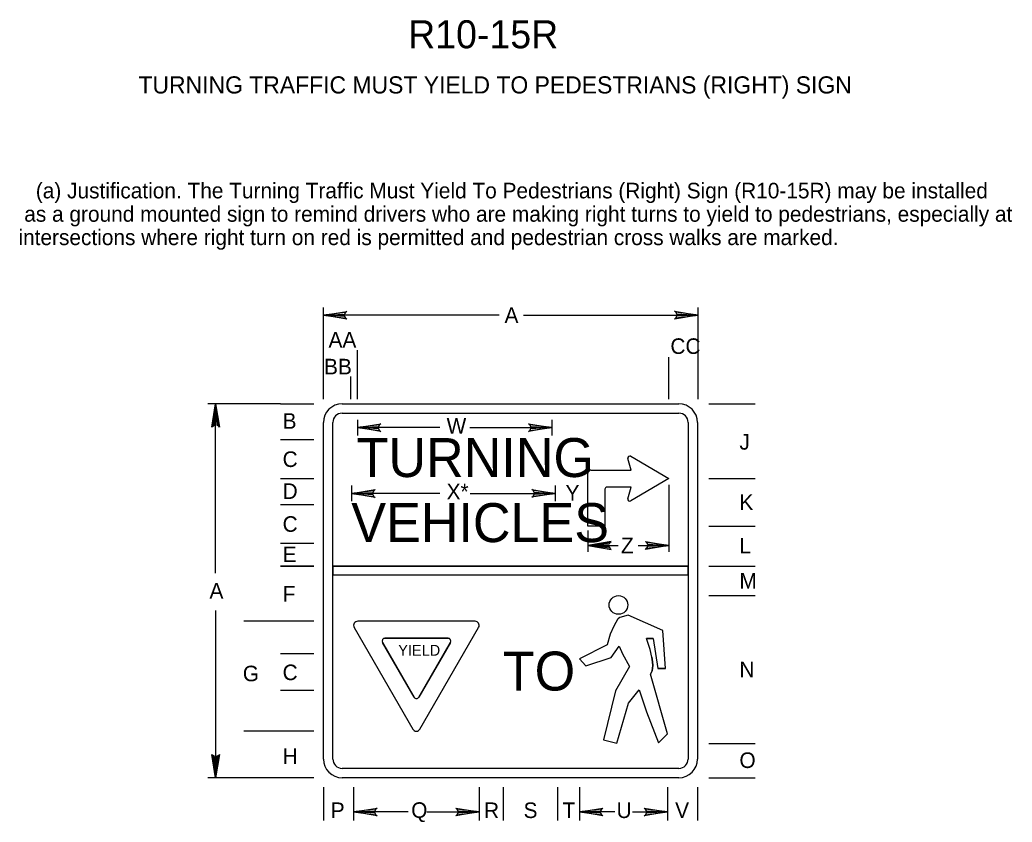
# Model space of a CAD drawing. Extents: x 0.013 to 0.195, y 0.003 to 0.259.
# Drawn here: x 0.0354 to 0.1946, y 0.1304 to 0.2592 of the extents above; entities that cross this region are included whole.
import ezdxf

# ---------------------------------------------------------------- set-up
doc = ezdxf.new("R2010")
doc.units = 0
for name, color, linetype in [('1', 7, 'Continuous'), ('11', 7, 'Continuous'), ('12', 7, 'Continuous'), ('2', 7, 'Continuous'), ('3', 7, 'Continuous')]:
    doc.layers.add(name, color=color, linetype=linetype)

# ---------------------------------------------------------------- blocks, each defined once
blk = doc.blocks.new('RARROW')
at = {"layer": '3'}
for p, q in [((-2.156, 0.28500000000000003), (-2.2665, 0.384625)), ((-2.2665, 0.384625), (0, 0)), ((0, 0), (-2.2665, -0.379125)), ((-2.156, 0.28500000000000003), (-2.075625, 0.12075)), ((0, 0), (-2.156, 0.28500000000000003)), ((-2.14975, -0.2705), (0, 0)), ((-2.075625, 0.12075), (0, 0)), ((0, 0), (-2.074, -0.108)), ((-2.2665, -0.379125), (-2.14975, -0.2705)), ((-2.074, -0.108), (-2.14975, -0.2705))]:
    blk.add_line(p, q, dxfattribs=at)

msp = doc.modelspace()

# ---------------------------------------------------------------- linework, layer by layer
at = {"layer": '11'}
for p, q in [((0.08714626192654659, 0.19757244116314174), (0.14114626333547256, 0.19757244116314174)), ((0.08414626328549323, 0.1405724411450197), (0.08414626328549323, 0.19457244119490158)), ((0.14414626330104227, 0.19457244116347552), (0.14414626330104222, 0.14057244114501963)), ((0.13352399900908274, 0.1869474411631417), (0.13298903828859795, 0.18879460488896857)), ((0.13344744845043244, 0.18915100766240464), (0.1395413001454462, 0.1855724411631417)), ((0.12654130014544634, 0.1779474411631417), (0.1265413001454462, 0.1864474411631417)), ((0.1270413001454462, 0.1869474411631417), (0.13352399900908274, 0.1869474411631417)), ((0.1395413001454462, 0.1855724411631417), (0.1334474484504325, 0.1819938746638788)), ((0.12929130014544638, 0.1838849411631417), (0.12929130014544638, 0.1779474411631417)), ((0.13352399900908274, 0.18419744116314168), (0.12960380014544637, 0.18419744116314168)), ((0.13298903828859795, 0.18235027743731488), (0.13352399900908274, 0.18419744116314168)), ((0.12929130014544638, 0.1779474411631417), (0.1265413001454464, 0.1779474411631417)), ((0.14114680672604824, 0.13757244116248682), (0.08714626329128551, 0.13757244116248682))]:
    msp.add_line(p, q, dxfattribs=at)
for centre, radius, start, end in [((0.08714626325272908, 0.19457244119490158), 0.002999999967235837, 90, 180), ((0.1411462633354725, 0.19457244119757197), 0.0029999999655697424, 0, 90), ((0.1332892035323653, 0.18888153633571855), 0.0003125, 59.57674888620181, 196.15164896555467), ((0.1270413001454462, 0.1864474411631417), 0.0005, 90, 180), ((0.12960380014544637, 0.1838849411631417), 0.0003125, 90, 180), ((0.13328920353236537, 0.18226334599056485), 0.0003125, 163.8483510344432, 300.4232511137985), ((0.08714626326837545, 0.1405724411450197), 0.0029999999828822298, 180, 270), ((0.14114626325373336, 0.1405724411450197), 0.003000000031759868, 270, 0)]:
    msp.add_arc(centre, radius, start, end, dxfattribs=at)
at = {"layer": '3'}
for p, q in [((0.08414367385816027, 0.19832244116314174), (0.08414367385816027, 0.21304199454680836)), ((0.11232555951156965, 0.21179199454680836), (0.08414367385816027, 0.21179199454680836)), ((0.11624734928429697, 0.21179199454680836), (0.14422597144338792, 0.21179199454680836)), ((0.14422597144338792, 0.19832244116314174), (0.14422597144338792, 0.21304199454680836)), ((0.08958818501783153, 0.19832244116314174), (0.08958818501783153, 0.206177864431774)), ((0.1395413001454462, 0.19832244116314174), (0.1395413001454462, 0.20505915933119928)), ((0.08853412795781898, 0.19832244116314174), (0.08853412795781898, 0.20194492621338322)), ((0.07725456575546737, 0.1975724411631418), (0.06559336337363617, 0.19757244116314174)), ((0.06621386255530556, 0.19382244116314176), (0.06684336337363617, 0.19757244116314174)), ((0.06684336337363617, 0.19757244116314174), (0.0663769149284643, 0.1940052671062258)), ((0.06664573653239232, 0.1941382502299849), (0.06684336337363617, 0.19757244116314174)), ((0.06684336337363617, 0.19757244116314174), (0.0670201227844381, 0.19414093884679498)), ((0.06728608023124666, 0.19401560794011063), (0.06684336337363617, 0.19757244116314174)), ((0.06684336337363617, 0.19757244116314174), (0.06746386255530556, 0.19382244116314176)), ((0.06684336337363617, 0.1704095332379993), (0.06684336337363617, 0.19757244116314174)), ((0.07725456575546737, 0.19757244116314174), (0.08260389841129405, 0.19757244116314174)), ((0.14597859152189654, 0.19757244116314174), (0.15337234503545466, 0.19757244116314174)), ((0.08714621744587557, 0.19607244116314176), (0.14114626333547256, 0.19607244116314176)), ((0.08564626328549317, 0.140572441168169), (0.08564626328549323, 0.19457244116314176)), ((0.08958818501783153, 0.19502509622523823), (0.08958818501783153, 0.19249982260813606)), ((0.12079452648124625, 0.19502509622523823), (0.12079452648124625, 0.19249982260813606)), ((0.14264626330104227, 0.19457244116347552), (0.14264626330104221, 0.14057244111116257)), ((0.0663769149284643, 0.1940052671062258), (0.06621386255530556, 0.19382244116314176)), ((0.0663769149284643, 0.1940052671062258), (0.06664573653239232, 0.1941382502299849)), ((0.0670201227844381, 0.19414093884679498), (0.06728608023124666, 0.19401560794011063)), ((0.06746386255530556, 0.19382244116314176), (0.06728608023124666, 0.19401560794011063)), ((0.0926263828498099, 0.19374917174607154), (0.08958818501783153, 0.19374917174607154)), ((0.10279613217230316, 0.19374917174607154), (0.08958818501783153, 0.19374917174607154)), ((0.1076093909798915, 0.19374917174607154), (0.12079452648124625, 0.19374917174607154)), ((0.07725456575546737, 0.1918396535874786), (0.08260389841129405, 0.1918396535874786)), ((0.07725456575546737, 0.18558926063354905), (0.08260389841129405, 0.18558926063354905)), ((0.14597859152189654, 0.1855724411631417), (0.15337234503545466, 0.18557221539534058)), ((0.0886643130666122, 0.18446330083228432), (0.0886643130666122, 0.18193802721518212)), ((0.10279613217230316, 0.18318737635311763), (0.0886643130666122, 0.18318737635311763)), ((0.0926263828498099, 0.18318737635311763), (0.08958818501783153, 0.18318737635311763)), ((0.10765501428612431, 0.18318802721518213), (0.12079452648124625, 0.18318802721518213)), ((0.12133060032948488, 0.18446330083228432), (0.12133060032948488, 0.18193802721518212)), ((0.1395413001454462, 0.18459410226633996), (0.1395413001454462, 0.1738092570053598)), ((0.07725456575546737, 0.1814033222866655), (0.08260389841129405, 0.1814033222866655)), ((0.1265413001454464, 0.1772487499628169), (0.1265413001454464, 0.1738092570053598)), ((0.14597859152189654, 0.1779474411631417), (0.15337234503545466, 0.1779474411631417)), ((0.07725456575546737, 0.17520995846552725), (0.08260389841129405, 0.17520995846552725)), ((0.1265413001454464, 0.17482786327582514), (0.13142869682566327, 0.17482786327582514)), ((0.13465260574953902, 0.17482786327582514), (0.13954000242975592, 0.17482786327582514)), ((0.07725456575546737, 0.1715372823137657), (0.08260389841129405, 0.1715372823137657)), ((0.08260389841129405, 0.17151328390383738), (0.07725456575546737, 0.17151328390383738)), ((0.08564626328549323, 0.17151328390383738), (0.14264626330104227, 0.17151328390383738)), ((0.08564626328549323, 0.17151328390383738), (0.14264626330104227, 0.17151328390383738)), ((0.14597859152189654, 0.1715372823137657), (0.15337234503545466, 0.1715372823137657)), ((0.08564626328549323, 0.1701387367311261), (0.14264626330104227, 0.1701387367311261)), ((0.14597859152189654, 0.16679245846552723), (0.15337234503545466, 0.16679245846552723)), ((0.06684336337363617, 0.16440728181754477), (0.06684336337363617, 0.13757244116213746)), ((0.08260389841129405, 0.16268525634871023), (0.07138468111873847, 0.16268525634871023)), ((0.10845774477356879, 0.16268525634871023), (0.0896450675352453, 0.16268525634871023)), ((0.13139105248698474, 0.16304309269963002), (0.1307183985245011, 0.16189648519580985)), ((0.13139105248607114, 0.16304309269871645), (0.1314746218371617, 0.16312666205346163)), ((0.13166439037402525, 0.16329738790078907), (0.13147462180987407, 0.16312666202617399)), ((0.13303157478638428, 0.16367847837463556), (0.13166439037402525, 0.16329738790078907)), ((0.13860080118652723, 0.16117027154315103), (0.13303157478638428, 0.16367847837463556)), ((0.08907250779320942, 0.1617037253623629), (0.09847884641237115, 0.14537214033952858)), ((0.09962396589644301, 0.14537214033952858), (0.10903030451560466, 0.1617037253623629)), ((0.1307183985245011, 0.16189648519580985), (0.1301372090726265, 0.1606256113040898)), ((0.13901126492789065, 0.15508652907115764), (0.13860080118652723, 0.16117027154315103)), ((0.09359845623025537, 0.15930442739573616), (0.09866969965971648, 0.1504979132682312)), ((0.10412264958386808, 0.15995878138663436), (0.09398016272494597, 0.15995878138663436)), ((0.09943311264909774, 0.1504979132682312), (0.10450435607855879, 0.15930442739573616)), ((0.1301372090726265, 0.1606256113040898), (0.12962866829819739, 0.1588826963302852)), ((0.13594911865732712, 0.15989939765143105), (0.13703885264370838, 0.15993570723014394)), ((0.1365666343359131, 0.1581564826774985), (0.13594911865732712, 0.15989939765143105)), ((0.13703885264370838, 0.15993570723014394), (0.1377912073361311, 0.15512137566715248)), ((0.13028250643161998, 0.1568492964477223), (0.13159018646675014, 0.15870114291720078)), ((0.13159018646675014, 0.15870114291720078), (0.13213505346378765, 0.1574302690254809)), ((0.1368439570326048, 0.15692897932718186), (0.1365666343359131, 0.1581564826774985)), ((0.08260389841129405, 0.15745674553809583), (0.07725456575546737, 0.15745674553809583)), ((0.1262133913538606, 0.15551470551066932), (0.13028250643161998, 0.1568492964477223)), ((0.13213505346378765, 0.1574302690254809), (0.13326110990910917, 0.15543317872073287)), ((0.13693632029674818, 0.15619034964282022), (0.1368439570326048, 0.15692897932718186)), ((0.1369653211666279, 0.15555974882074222), (0.13693632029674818, 0.15619034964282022)), ((0.13326110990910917, 0.15543317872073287), (0.1309937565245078, 0.1515322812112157)), ((0.13661346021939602, 0.15418801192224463), (0.13686855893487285, 0.1547331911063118)), ((0.13686855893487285, 0.1547331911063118), (0.1369653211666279, 0.15555974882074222)), ((0.1377912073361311, 0.15512137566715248), (0.13901126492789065, 0.15508652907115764)), ((0.13933463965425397, 0.14461041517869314), (0.13661346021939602, 0.15418801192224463)), ((0.08260389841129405, 0.15156691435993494), (0.07725456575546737, 0.15156691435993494)), ((0.1309937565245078, 0.1515322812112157), (0.12907652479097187, 0.14365718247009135)), ((0.13305042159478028, 0.14951123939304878), (0.13478673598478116, 0.15165686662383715)), ((0.13478673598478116, 0.15165686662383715), (0.135985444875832, 0.14817103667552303)), ((0.13120290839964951, 0.14309965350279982), (0.13305042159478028, 0.14951123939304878)), ((0.135985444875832, 0.14817103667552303), (0.13788983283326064, 0.1431478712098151)), ((0.08260389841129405, 0.14504147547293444), (0.07138468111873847, 0.14504147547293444)), ((0.12907652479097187, 0.14365718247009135), (0.13120290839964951, 0.14309965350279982)), ((0.13788983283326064, 0.1431478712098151), (0.13933463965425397, 0.14461041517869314)), ((0.14597859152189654, 0.14307974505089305), (0.15337234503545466, 0.14307974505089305)), ((0.14114664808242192, 0.13907244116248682), (0.08714626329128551, 0.13907244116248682)), ((0.07725456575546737, 0.13757244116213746), (0.06559336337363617, 0.13757244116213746)), ((0.08260389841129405, 0.13757244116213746), (0.07725456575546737, 0.13757244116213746)), ((0.14597859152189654, 0.1375724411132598), (0.15337234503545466, 0.1375724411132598)), ((0.08414626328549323, 0.13604448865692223), (0.08414626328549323, 0.13070656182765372)), ((0.0889899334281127, 0.13604448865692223), (0.0889907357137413, 0.13070656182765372)), ((0.10911631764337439, 0.13604448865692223), (0.10911624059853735, 0.13070656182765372)), ((0.11299472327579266, 0.13604448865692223), (0.11299472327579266, 0.13070656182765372)), ((0.12166315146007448, 0.13604448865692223), (0.12166315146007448, 0.13070656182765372)), ((0.12523045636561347, 0.13604448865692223), (0.12523045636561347, 0.13070656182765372)), ((0.13933463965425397, 0.13604448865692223), (0.13933463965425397, 0.13070656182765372)), ((0.14414626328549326, 0.13604448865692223), (0.14414626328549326, 0.13070656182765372)), ((0.09775368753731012, 0.1320796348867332), (0.08899052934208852, 0.1320796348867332)), ((0.1007284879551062, 0.13207591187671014), (0.10911626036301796, 0.13207591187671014)), ((0.13088887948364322, 0.1320796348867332), (0.12522462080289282, 0.1320796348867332)), ((0.1337444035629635, 0.13207591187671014), (0.13933463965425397, 0.13207591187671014))]:
    msp.add_line(p, q, dxfattribs=at)
for points in [[(0.08564626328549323, 0.1701387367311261), (0.14264626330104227, 0.1701387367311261), (0.1426462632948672, 0.17151328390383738), (0.08564626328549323, 0.17151328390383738), (0.08564626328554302, 0.1701387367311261)], [(0.10845774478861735, 0.1626852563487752), (0.0896450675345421, 0.16268525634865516)], [(0.08907250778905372, 0.16170372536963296), (0.09847884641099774, 0.14537214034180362)], [(0.09962396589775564, 0.14537214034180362), (0.10903030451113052, 0.16170372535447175)], [(0.09867564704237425, 0.15050856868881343), (0.09360463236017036, 0.1592930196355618)], [(0.09398249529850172, 0.1599472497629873), (0.10412502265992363, 0.1599472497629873)], [(0.10450293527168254, 0.15929310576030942), (0.0994309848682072, 0.15050896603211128)], [(0.13703885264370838, 0.15993570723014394), (0.13594911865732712, 0.15989939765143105), (0.13703885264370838, 0.15993570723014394)], [(0.12962866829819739, 0.1588826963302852), (0.12523045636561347, 0.15663506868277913), (0.1262133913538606, 0.15551470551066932)], [(0.1368439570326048, 0.15692897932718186), (0.13693632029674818, 0.15619034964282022), (0.1369653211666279, 0.15555974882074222), (0.13686855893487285, 0.1547331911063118), (0.13661346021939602, 0.15418801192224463), (0.13686855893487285, 0.1547331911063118), (0.1369653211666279, 0.15555974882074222), (0.13693632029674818, 0.15619034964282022), (0.1368439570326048, 0.15692897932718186)], [(0.13901126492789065, 0.15508652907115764), (0.1377912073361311, 0.15512137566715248), (0.13901126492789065, 0.15508652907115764)]]:
    msp.add_lwpolyline(points, dxfattribs=at)
msp.add_circle((0.1314666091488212, 0.16529132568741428), 0.0014959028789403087, dxfattribs=at)
for centre, radius, start, end in [((0.08714626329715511, 0.19457244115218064), 0.0015000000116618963, 90, 180), ((0.14114626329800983, 0.19457244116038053), 0.001500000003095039, 0, 90), ((0.08964201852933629, 0.16202927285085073), 0.0006559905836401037, 89.73369166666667, 209.75343333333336), ((0.08964201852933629, 0.16202927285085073), 0.0006559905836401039, 89.73369166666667, 209.75343333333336), ((0.10846057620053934, 0.16202914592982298), 0.0006561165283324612, 330.2656166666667, 90.24725555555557), ((0.10846057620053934, 0.16202914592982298), 0.0006561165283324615, 330.2656166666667, 90.24725555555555), ((0.09398249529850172, 0.1595110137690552), 0.0004362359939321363, 90, 209.98121666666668), ((0.09398249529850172, 0.1595110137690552), 0.0004362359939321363, 89.99999999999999, 209.98121666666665), ((0.10412502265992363, 0.1595110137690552), 0.0004362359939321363, 330.03184166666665, 90), ((0.10412502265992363, 0.1595110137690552), 0.0004362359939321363, 330.03184166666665, 89.99999999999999), ((0.0990532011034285, 0.15072709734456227), 0.00043623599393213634, 210.0623, 329.99798055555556), ((0.0990532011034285, 0.15072709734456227), 0.0004362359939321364, 210.06229999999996, 329.9979805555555), ((0.09905140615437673, 0.14570251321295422), 0.0006610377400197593, 209.9853888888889, 330.0146111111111), ((0.09905140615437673, 0.14570251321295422), 0.0006610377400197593, 209.98538888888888, 330.0146111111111), ((0.08714626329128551, 0.140572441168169), 0.001500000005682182, 180, 270), ((0.14114626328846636, 0.14057244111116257), 0.0014999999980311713, 270, 0)]:
    msp.add_arc(centre, radius, start, end, dxfattribs=at)

# ---------------------------------------------------------------- block references
at = {"layer": '3', "xscale": 0.0016545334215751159}
for p, yscale, rotation in [((0.08414367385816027, 0.21179199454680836), 0.0016366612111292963, 180), ((0.08958818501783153, 0.19374917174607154), 0.0016366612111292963, 180), ((0.0886643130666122, 0.18318737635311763), 0.0016366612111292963, 180), ((0.1265413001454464, 0.17482786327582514), -0.0016366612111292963, 180), ((0.06684336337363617, 0.13757244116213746), 0.0016366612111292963, -90), ((0.08899052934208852, 0.1320796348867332), 0.0016366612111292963, 180), ((0.12522462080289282, 0.1320796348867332), 0.0016366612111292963, 180)]:
    msp.add_blockref('RARROW', p, dxfattribs=dict(at, yscale=yscale, rotation=rotation))
at = {"layer": '3', "xscale": 0.0016545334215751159, "yscale": 0.0016366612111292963}
for p in [(0.14422597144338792, 0.21179199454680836), (0.1207945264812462, 0.19374917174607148), (0.12133060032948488, 0.18318802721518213), (0.13954000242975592, 0.17482786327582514), (0.10911626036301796, 0.13207591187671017), (0.13933463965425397, 0.13207591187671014)]:
    msp.add_blockref('RARROW', p, dxfattribs=at)

# ---------------------------------------------------------------- texts
at = {"layer": '1'}
for s, height, p in [('R10-15R', 0.0045000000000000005, (0.09772772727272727, 0.254625)), ('TURNING TRAFFIC MUST YIELD TO PEDESTRIANS (RIGHT) SIGN', 0.00275025, (0.05447118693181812, 0.247375))]:
    msp.add_text(s, height=height, dxfattribs=at).set_placement(p)
at = {"layer": '12'}
for s, p in [('TURNING', (0.08946536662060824, 0.18582526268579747)), ('VEHICLES', (0.08861025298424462, 0.17538260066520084)), ('TO', (0.11291575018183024, 0.15156490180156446))]:
    msp.add_text(s, height=0.0062499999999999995, dxfattribs=at).set_placement(p)
at = {"layer": '2'}
for s, p in [('   (a) Justification. The Turning Traffic Must Yield To Pedestrians (Right) Sign (R10-15R) may be installed ', (0.03522071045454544, 0.23054097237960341)), (' as a ground mounted sign to remind drivers who are making right turns to yield to pedestrians, especially at ', (0.03522071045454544, 0.2267912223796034)), ('intersections where right turn on red is permitted and pedestrian cross walks are marked.', (0.03522071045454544, 0.22304147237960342))]:
    msp.add_text(s, height=0.0024997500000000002, dxfattribs=at).set_placement(p)
at = {"layer": '3'}
for s, height, p in [('A', 0.0025, (0.11319020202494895, 0.21054199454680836)), ('AA', 0.0025, (0.08496031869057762, 0.20659481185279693)), ('CC', 0.0025, (0.13979731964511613, 0.2055789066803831)), ('BB', 0.0025, (0.08423998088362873, 0.20229535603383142)), ('B', 0.0024997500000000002, (0.07759461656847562, 0.19357244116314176)), ('W', 0.0024997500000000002, (0.10389916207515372, 0.19280074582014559)), ('J', 0.0024997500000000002, (0.15087234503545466, 0.19021833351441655)), ('C', 0.0024997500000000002, (0.07759461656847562, 0.18743610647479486)), ('D', 0.0024997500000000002, (0.07759461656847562, 0.1823043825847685)), ('X*', 0.0024997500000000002, (0.10389916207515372, 0.18223895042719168)), ('Y', 0.0024997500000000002, (0.12297645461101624, 0.18203197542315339)), ('K', 0.0024997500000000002, (0.15087234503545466, 0.1805366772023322)), ('C', 0.0024997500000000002, (0.07759461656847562, 0.17703489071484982)), ('Z', 0.0024997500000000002, (0.131871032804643, 0.17358989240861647)), ('L', 0.0024997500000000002, (0.15087234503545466, 0.17356751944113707)), ('E', 0.0024997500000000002, (0.07759461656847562, 0.17217600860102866)), ('M', 0.0024997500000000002, (0.15087234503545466, 0.16793064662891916)), ('A', 0.0024997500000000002, (0.06586503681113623, 0.16632256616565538)), ('F', 0.0024997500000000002, (0.07759461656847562, 0.165834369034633)), ('YIELD', 0.001744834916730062, (0.09613407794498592, 0.15715051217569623)), ('N', 0.0024997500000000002, (0.15087234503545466, 0.15368622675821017)), ('G', 0.0024997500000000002, (0.0712089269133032, 0.15304887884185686)), ('C', 0.0024997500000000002, (0.07759461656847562, 0.15323029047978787)), ('H', 0.0024997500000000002, (0.07759461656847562, 0.13979700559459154)), ('O', 0.0024997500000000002, (0.15087234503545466, 0.13913239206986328)), ('P', 0.0024997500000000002, (0.08531165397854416, 0.13110269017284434)), ('Q', 0.0024997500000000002, (0.09822366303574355, 0.13112683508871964)), ('R', 0.0024997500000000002, (0.10990261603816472, 0.13110269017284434)), ('S', 0.0024997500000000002, (0.11624425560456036, 0.13110269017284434)), ('T', 0.0024997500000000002, (0.12249345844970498, 0.13110269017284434)), ('U', 0.0024997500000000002, (0.13116307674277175, 0.13110269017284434)), ('V', 0.0024997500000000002, (0.14056147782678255, 0.13110269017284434))]:
    msp.add_text(s, height=height, dxfattribs=at).set_placement(p)

doc.saveas('drawing.dxf')
